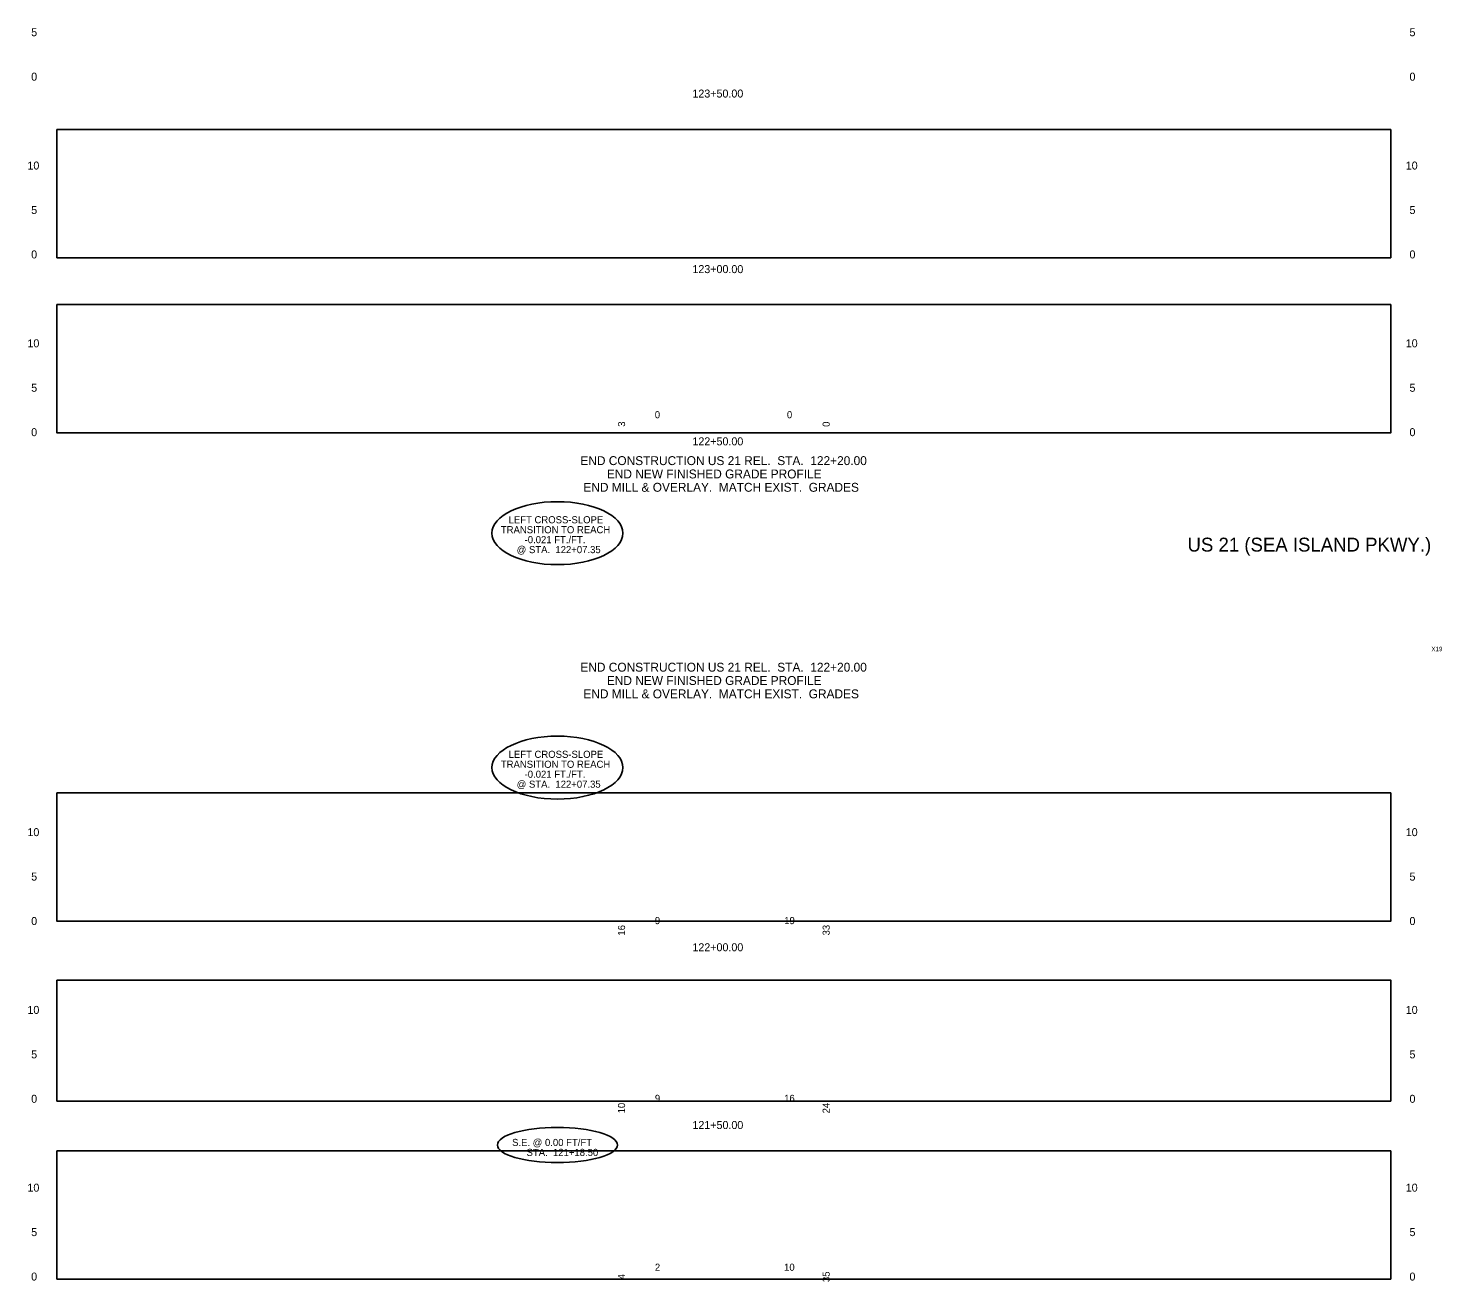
# Model space of a CAD drawing. Extents: x 971 to 1131, y 2203 to 6043.
# Drawn here: x 971.5 to 1130.5, y 5751.7 to 5892.8 of the extents above; entities that cross this region are included whole.
import ezdxf

# ---------------------------------------------------------------- set-up
doc = ezdxf.new("R2010")
doc.units = 0
for name, color, linetype in [('RD_SHT_Misc1', 7, 'Continuous'), ('RD_SHT_ShtClip', 7, 'Continuous'), ('RD_SHT_TX', 7, 'Continuous'), ('RD_TX_StaOff', 7, 'Continuous'), ('RD_XS_TX_Station', 7, 'Continuous')]:
    doc.layers.add(name, color=color, linetype=linetype)

msp = doc.modelspace()

# ---------------------------------------------------------------- linework, layer by layer
at = {"layer": 'RD_SHT_ShtClip'}
for points in [[(974.73, 5881.37), (1124.73, 5881.37), (1124.73, 5866.94), (974.73, 5866.94)], [(974.73, 5861.67), (1124.73, 5861.67), (1124.73, 5847.24), (974.73, 5847.24)], [(974.73, 5806.73), (1124.73, 5806.73), (1124.73, 5792.3), (974.73, 5792.3)], [(974.73, 5785.68), (1124.73, 5785.68), (1124.73, 5772.07), (974.73, 5772.07)], [(974.73, 5766.46), (1124.73, 5766.46), (1124.73, 5752.03), (974.73, 5752.03)]]:
    msp.add_lwpolyline(points, close=True, dxfattribs=at)
at = {"layer": 'RD_TX_StaOff'}
for centre, major_axis, ratio in [((1031.02, 5835.96), (7.37, 0), 0.480649), ((1031.02, 5809.58), (7.37, 0), 0.480649), ((1031.02, 5767.12), (-6.75, 0), 0.293299)]:
    msp.add_ellipse(centre, major_axis=major_axis, ratio=ratio, dxfattribs=at)

# ---------------------------------------------------------------- texts
at = {"layer": 'RD_SHT_Misc1'}
for s, p in [('0', (1041.97, 5848.89)), ('0', (1056.83, 5848.89)), ('9', (1041.98, 5791.97)), ('19', (1056.53, 5791.97)), ('9', (1041.98, 5771.97)), ('16', (1056.52, 5771.97)), ('2', (1041.98, 5752.97)), ('10', (1056.51, 5752.97))]:
    msp.add_text(s, height=0.8, dxfattribs=at).set_placement(p)
for s, p in [('3', (1038.63, 5847.93)), ('0', (1061.64, 5847.92)), ('16', (1038.63, 5790.68)), ('33', (1061.64, 5790.7)), ('10', (1038.63, 5770.68)), ('24', (1061.64, 5770.68)), ('4', (1038.63, 5752)), ('35', (1061.64, 5751.7))]:
    msp.add_text(s, height=0.8, rotation=90, dxfattribs=at).set_placement(p)
at = {"layer": 'RD_SHT_TX'}
for s, height, p in [('5', 0.9, (971.84, 5891.87)), ('5', 0.9, (1126.84, 5891.87)), ('0', 0.9, (971.84, 5886.87)), ('0', 0.9, (1126.84, 5886.87)), ('10', 0.9, (971.42, 5876.87)), ('10', 0.9, (1126.42, 5876.87)), ('5', 0.9, (971.84, 5871.87)), ('5', 0.9, (1126.84, 5871.87)), ('0', 0.9, (971.84, 5866.87)), ('0', 0.9, (1126.84, 5866.87)), ('10', 0.9, (971.42, 5856.87)), ('10', 0.9, (1126.42, 5856.87)), ('5', 0.9, (971.84, 5851.87)), ('5', 0.9, (1126.84, 5851.87)), ('0', 0.9, (971.84, 5846.87)), ('0', 0.9, (1126.84, 5846.87)), ('US 21 (SEA ISLAND PKWY.)', 1.5625, (1101.88, 5833.89)), ('10', 0.9, (971.42, 5801.87)), ('10', 0.9, (1126.42, 5801.87)), ('5', 0.9, (971.84, 5796.87)), ('5', 0.9, (1126.84, 5796.87)), ('0', 0.9, (971.84, 5791.87)), ('0', 0.9, (1126.84, 5791.87)), ('10', 0.9, (971.42, 5781.87)), ('10', 0.9, (1126.42, 5781.87)), ('5', 0.9, (971.84, 5776.87)), ('5', 0.9, (1126.84, 5776.87)), ('0', 0.9, (971.84, 5771.87)), ('0', 0.9, (1126.84, 5771.87)), ('10', 0.9, (971.42, 5761.87)), ('10', 0.9, (1126.42, 5761.87)), ('5', 0.9, (971.84, 5756.87)), ('5', 0.9, (1126.84, 5756.87)), ('0', 0.9, (971.84, 5751.87)), ('0', 0.9, (1126.84, 5751.87))]:
    msp.add_text(s, height=height, dxfattribs=at).set_placement(p)
msp.add_text('X19', height=0.5, rotation=360, dxfattribs=at).set_placement((1129.31, 5822.68))
at = {"layer": 'RD_TX_StaOff'}
for s, height, p in [('END CONSTRUCTION US 21 REL.  STA.  122+20.00', 1, (1033.6, 5843.62)), ('END NEW FINISHED GRADE PROFILE', 1, (1036.58, 5842.12)), ('END MILL & OVERLAY.  MATCH EXIST.  GRADES', 1, (1033.94, 5840.62)), ('TRANSITION TO REACH', 0.8, (1024.66, 5835.95)), ('LEFT CROSS-SLOPE', 0.8, (1025.53, 5837.07)), ('-0.021 FT./FT.', 0.8, (1027.33, 5834.83)), ('@ STA.  122+07.35', 0.8, (1026.44, 5833.71)), ('END CONSTRUCTION US 21 REL.  STA.  122+20.00', 1, (1033.6, 5820.38)), ('END NEW FINISHED GRADE PROFILE', 1, (1036.58, 5818.88)), ('END MILL & OVERLAY.  MATCH EXIST.  GRADES', 1, (1033.94, 5817.38)), ('LEFT CROSS-SLOPE', 0.8, (1025.53, 5810.68)), ('TRANSITION TO REACH', 0.8, (1024.66, 5809.56)), ('@ STA.  122+07.35', 0.8, (1026.44, 5807.32)), ('-0.021 FT./FT.', 0.8, (1027.33, 5808.44))]:
    msp.add_text(s, height=height, dxfattribs=at).set_placement(p)
for s, p in [('S.E. @ 0.00 FT/FT', (1025.92, 5767.01)), ('STA.  121+18.50', (1027.55, 5765.89))]:
    msp.add_text(s, height=0.8, rotation=360, dxfattribs=at).set_placement(p)
at = {"layer": 'RD_XS_TX_Station'}
for s, p in [('123+50.00', (1046.2, 5884.97)), ('123+00.00', (1046.2, 5865.22)), ('122+50.00', (1046.2, 5845.84)), ('122+00.00', (1046.2, 5788.92)), ('121+50.00', (1046.2, 5768.92))]:
    msp.add_text(s, height=0.9, dxfattribs=at).set_placement(p)

doc.saveas('drawing.dxf')
